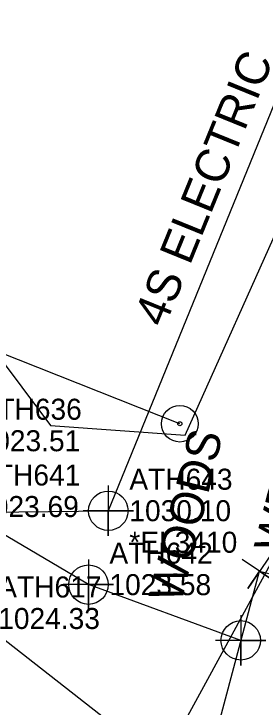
# Model space of a CAD drawing. Extents: x 1212084 to 1214478, y 765637 to 767408.
# Drawn here: x 1213289.6 to 1213319, y 766500.6 to 766583.1 of the extents above; entities that cross this region are included whole.
import ezdxf

# ---------------------------------------------------------------- set-up
doc = ezdxf.new("R2010")
doc.units = 0
for name, color, linetype in [('Exist Environmental Wetland Boundary Cogo Elevation', 7, 'Continuous'), ('Exist Environmental Wetland Boundary Cogo Number', 7, 'Continuous'), ('Exist Environmental Wetland Boundary Cogo Point CELL', 7, 'Continuous'), ('Exist Hydro Jurisdictional Stream or Body of Water', 7, 'Continuous'), ('Exist Other Culture Fence Line', 7, 'Continuous'), ('Exist Other Culture Fence Line Cogo Comment', 7, 'Continuous'), ('Exist Other Culture Fence Line Cogo Elevation', 7, 'Continuous'), ('Exist Other Culture Fence Line Cogo Number', 7, 'Continuous'), ('Exist Other Culture Fence Line Cogo Point CELL', 7, 'Continuous'), ('Exist Other Culture Fence Line Text', 7, 'Continuous'), ('Exist Property Corner CELL', 7, 'Continuous'), ('Exist Right of Way Line', 7, 'Continuous'), ('Exist Structure Major Bridge WW Text', 7, 'Continuous'), ('Exist Utilities Other Located Object CELL', 7, 'Continuous'), ('Exist Utilities Other Located Object Text', 7, 'Continuous'), ('Exist Vegetation Woods Line', 7, 'Continuous'), ('Exist Vegetation Woods Line Text', 7, 'Continuous')]:
    doc.layers.add(name, color=color, linetype=linetype)

msp = doc.modelspace()

# ---------------------------------------------------------------- linework, layer by layer
at = {"layer": 'Exist Environmental Wetland Boundary Cogo Point CELL'}
for points in [[(1213298.428, 766518.156), (1213298.428, 766512.156), (1213298.428, 766515.156), (1213301.428, 766515.156), (1213295.428, 766515.156)], [(1213316.525, 766511.528), (1213316.525, 766505.528), (1213316.525, 766508.528), (1213319.525, 766508.528), (1213313.525, 766508.528)]]:
    msp.add_lwpolyline(points, dxfattribs=at)
for centre in [(1213298.428, 766515.156), (1213316.525, 766508.528)]:
    msp.add_circle(centre, 2.344, dxfattribs=at)
at = {"layer": 'Exist Hydro Jurisdictional Stream or Body of Water'}
for points in [[(1213316.525, 766508.528), (1213298.428, 766515.156), (1213282.707, 766524.453), (1213282.877, 766532.283), (1213254.919, 766547.163), (1213231.611, 766558.456)], [(1213227.09, 766533.988), (1213261.681, 766524.754), (1213285.214, 766511.13), (1213309.319, 766492.246)]]:
    msp.add_lwpolyline(points, dxfattribs=at)
at = {"layer": 'Exist Other Culture Fence Line'}
for points in [[(1213233.32, 766620.626), (1213262.701, 766616.745), (1213306.285, 766606.368), (1213326.505, 766587.151), (1213300.794, 766523.955)], [(1213229.438, 766526.88), (1213261.802, 766523.492), (1213300.794, 766523.955)]]:
    msp.add_lwpolyline(points, dxfattribs=at)
at = {"layer": 'Exist Other Culture Fence Line Cogo Point CELL'}
msp.add_lwpolyline([(1213300.794, 766526.955), (1213300.794, 766520.955), (1213300.794, 766523.955), (1213303.794, 766523.955), (1213297.794, 766523.955)], dxfattribs=at)
msp.add_circle((1213300.794, 766523.955), 2.344, dxfattribs=at)
at = {"layer": 'Exist Property Corner CELL'}
msp.add_line((1213318.765, 766516.76), (1213318.765, 766516.76), dxfattribs=at)
msp.add_lwpolyline([(1213320.166, 766518.831), (1213317.365, 766514.689), (1213318.765, 766516.76), (1213320.836, 766515.359), (1213316.695, 766518.161)], dxfattribs=at)
at = {"layer": 'Exist Right of Way Line'}
for p, q in [((1213307.903, 766475.937), (1213318.765, 766516.76)), ((1213318.765, 766516.76), (1213324.08, 766515.346))]:
    msp.add_line(p, q, dxfattribs=at)
at = {"layer": 'Exist Utilities Other Located Object CELL'}
for radius in [2.18, 0.24]:
    msp.add_circle((1213309.289, 766534.307), radius, dxfattribs=at)
at = {"layer": 'Exist Utilities Other Located Object Text'}
msp.add_line((1213309.289, 766534.307), (1213178.617, 766586.151), dxfattribs=at)
at = {"layer": 'Exist Vegetation Woods Line'}
for points in [[(1213321.909, 766559.774), (1213329.044, 766580.902), (1213334.181, 766588.61), (1213339.033, 766584.042), (1213320.768, 766518.947), (1213308.496, 766496.393), (1213292.199, 766497.632)], [(1213218.886, 766546.641), (1213255.986, 766561.487), (1213283.668, 766547.783), (1213293.942, 766534.079), (1213309.923, 766532.937), (1213321.909, 766559.774)]]:
    msp.add_lwpolyline(points, dxfattribs=at)

# ---------------------------------------------------------------- texts
at = {"layer": 'Exist Environmental Wetland Boundary Cogo Elevation'}
for s, p in [('1023.51', (1213285.377, 766531.033)), ('1023.69', (1213285.207, 766523.203)), ('1023.58', (1213300.928, 766513.906)), ('1024.33', (1213287.714, 766509.88))]:
    msp.add_text(s, height=2.5, dxfattribs=at).set_placement(p)
at = {"layer": 'Exist Environmental Wetland Boundary Cogo Number'}
for s, p in [('ATH636', (1213285.377, 766534.783)), ('ATH641', (1213285.207, 766526.953)), ('ATH642', (1213300.928, 766517.656)), ('ATH617', (1213287.714, 766513.63))]:
    msp.add_text(s, height=2.5, dxfattribs=at).set_placement(p)
at = {"layer": 'Exist Other Culture Fence Line Cogo Comment'}
msp.add_text('*EL3410', height=2.5, dxfattribs=at).set_placement((1213303.294, 766518.955))
at = {"layer": 'Exist Other Culture Fence Line Cogo Elevation'}
msp.add_text('1030.10', height=2.5, dxfattribs=at).set_placement((1213303.294, 766522.705))
at = {"layer": 'Exist Other Culture Fence Line Cogo Number'}
msp.add_text('ATH643', height=2.5, dxfattribs=at).set_placement((1213303.294, 766526.455))
at = {"layer": 'Exist Other Culture Fence Line Text'}
msp.add_text('4S ELECTRIC', height=4, rotation=67.86128, dxfattribs=at).set_placement((1213307.452, 766545.628))
at = {"layer": 'Exist Structure Major Bridge WW Text'}
msp.add_text('WD WW', height=4, rotation=75.52752, dxfattribs=at).set_placement((1213321.932, 766518.685))
at = {"layer": 'Exist Vegetation Woods Line Text'}
msp.add_text('WOODS', height=4, rotation=76.13927, dxfattribs=at).set_placement((1213309.433, 766512.815))

doc.saveas('drawing.dxf')
